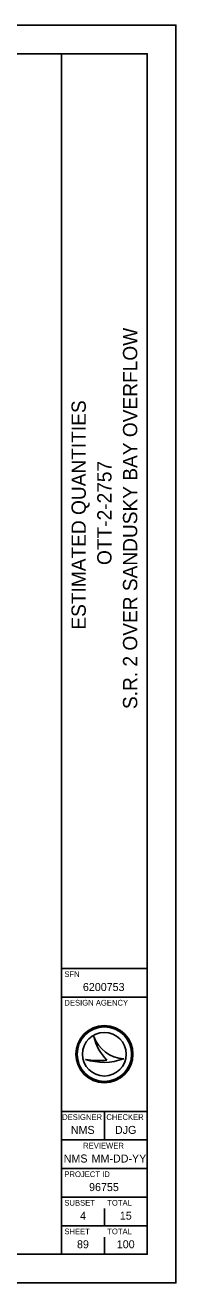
# Model space of a CAD drawing. Extents: x 0 to 47.9, y 0 to 22.
# Drawn here: x 31.36 to 34, y 0 to 22 of the extents above; entities that cross this region are included whole.
import ezdxf

# ---------------------------------------------------------------- set-up
doc = ezdxf.new("R2010")
doc.units = 0
for name, color, linetype in [('SH_Border', 7, 'Continuous'), ('SH_Cut_Line', 7, 'Continuous'), ('SH_Data', 7, 'Continuous')]:
    doc.layers.add(name, color=color, linetype=linetype)

msp = doc.modelspace()

# ---------------------------------------------------------------- linework, layer by layer
at = {"layer": 'SH_Border'}
for p, q in [((32, 0.5), (32, 21.5)), ((32, 5.5), (33.5, 5.5)), ((32, 5), (33.5, 5)), ((32, 3), (33.5, 3)), ((32.75, 3), (32.75, 2.5)), ((32, 2.5), (33.5, 2.5)), ((32, 2), (33.5, 2)), ((32, 1.5), (33.5, 1.5)), ((32, 1), (33.5, 1))]:
    msp.add_line(p, q, dxfattribs=at)
msp.add_lwpolyline([(1.5, 21.5), (33.5, 21.5), (33.5, 0.5), (1.5, 0.5)], close=True, dxfattribs=at)
at = {"layer": 'SH_Cut_Line'}
msp.add_lwpolyline([(0, 0), (34, 0), (34, 22), (0, 22)], close=True, dxfattribs=at)
at = {"layer": 'SH_Data'}
for p, q in [((32.567, 4.31), (32.567, 4.31)), ((32.75, 4), (32.75, 4)), ((32.417, 3.91), (32.417, 3.91)), ((33.087, 3.919), (33.087, 3.919)), ((32.75, 1), (32.75, 1.3)), ((32.375, 0.675), (32.375, 0.675)), ((32.75, 0.5), (32.75, 0.8))]:
    msp.add_line(p, q, dxfattribs=at)
for radius in [0.5, 0.477, 0.477, 0.382]:
    msp.add_circle((32.75, 4), radius, dxfattribs=at)
for centre, radius, start, end in [((33.116, 4.498), 0.58, 198.9257, 198.9319), ((33.347, 4.47), 0.796, 191.6379, 191.6421), ((33.116, 4.498), 0.58, 198.9319, 267.1657), ((33.347, 4.47), 0.796, 191.6421, 226.0947), ((32.739, 4.87), 1.013, 251.4576, 290.0832), ((32.648, 5.154), 1.266, 259.4964, 259.4995), ((32.739, 4.87), 1.013, 251.4527, 251.4576), ((32.648, 5.154), 1.266, 259.4995, 276.6672)]:
    msp.add_arc(centre, radius, start, end, dxfattribs=at)

# ---------------------------------------------------------------- texts
for s, p in [('S.R. 2 OVER SANDUSKY BAY OVERFLOW', (33.325, 10.037)), ('ESTIMATED QUANTITIES', (32.425, 11.426)), ('OTT-2-2757', (32.875, 12.557))]:
    msp.add_text(s, height=0.25, rotation=90, dxfattribs=at).set_placement(p)
for s, height, p in [('SFN', 0.1, (32.05, 5.35)), ('6200753', 0.14, (32.374, 5.105)), ('DESIGN AGENCY', 0.1, (32.05, 4.85)), ('DESIGNER', 0.1, (32.011, 2.85)), ('CHECKER', 0.1, (32.784, 2.85)), ('NMS', 0.14, (32.163, 2.605)), ('DJG', 0.14, (32.935, 2.605)), ('REVIEWER', 0.1, (32.378, 2.35)), ('NMS', 0.14, (32.038, 2.105)), ('MM-DD-YY', 0.14, (32.526, 2.105)), ('PROJECT ID', 0.1, (32.05, 1.85)), ('96755', 0.14, (32.482, 1.605)), ('SUBSET', 0.1, (32.05, 1.35)), ('TOTAL', 0.1, (32.8, 1.35)), ('4', 0.14, (32.325, 1.105)), ('15', 0.14, (33.02, 1.105)), ('SHEET', 0.1, (32.05, 0.85)), ('TOTAL', 0.1, (32.8, 0.85)), ('89', 0.14, (32.271, 0.605)), ('100', 0.14, (32.967, 0.605))]:
    msp.add_text(s, height=height, dxfattribs=at).set_placement(p)

doc.saveas('drawing.dxf')
